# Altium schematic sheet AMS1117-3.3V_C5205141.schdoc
size 127 x 101 mm
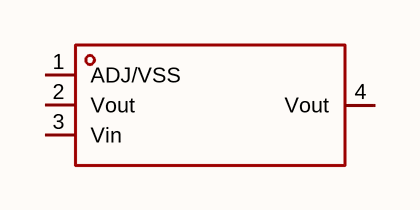
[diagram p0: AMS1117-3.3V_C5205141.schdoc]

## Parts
U?  ams1117-3.3v_c5205141  [SOT-223-3_L6.5-W3.4-P2.30-LS7.0-BR]  (value not drawn)

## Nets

Not connected (* = marked no-connect by the designer): U? 1(ADJ/VSS) 2(Vout) 3(Vin) 4(Vout)

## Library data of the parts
U? = ams1117-3.3v_c5205141: 输出极性:正极;工作电压:15V;输出电压:3.3V;输出电流:1.2A;电源纹波抑制比(PSRR):-;输出类型:固定;; Manufacturer: JSMSEMI(杰盛微); AddInBom: yes; ModelId: 925194bf9823436183a3e0b978a8d076; ModelName: SOT-223-4P_L6.5-W3.5-H1.6-LS7.0-P2.30; ModelTransform: 279.89794,255.905,0,180,0,0,-3.9385,-0.0005,0; Output Configuration: 正极; Voltage - Supply: 15V; Output Voltage: 3.3V; Output Current: 1.2A; Voltage Dropout: 1.5V@(800mA); standby current: 5mA; Output Type: 固定; Number of Outputs: 1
